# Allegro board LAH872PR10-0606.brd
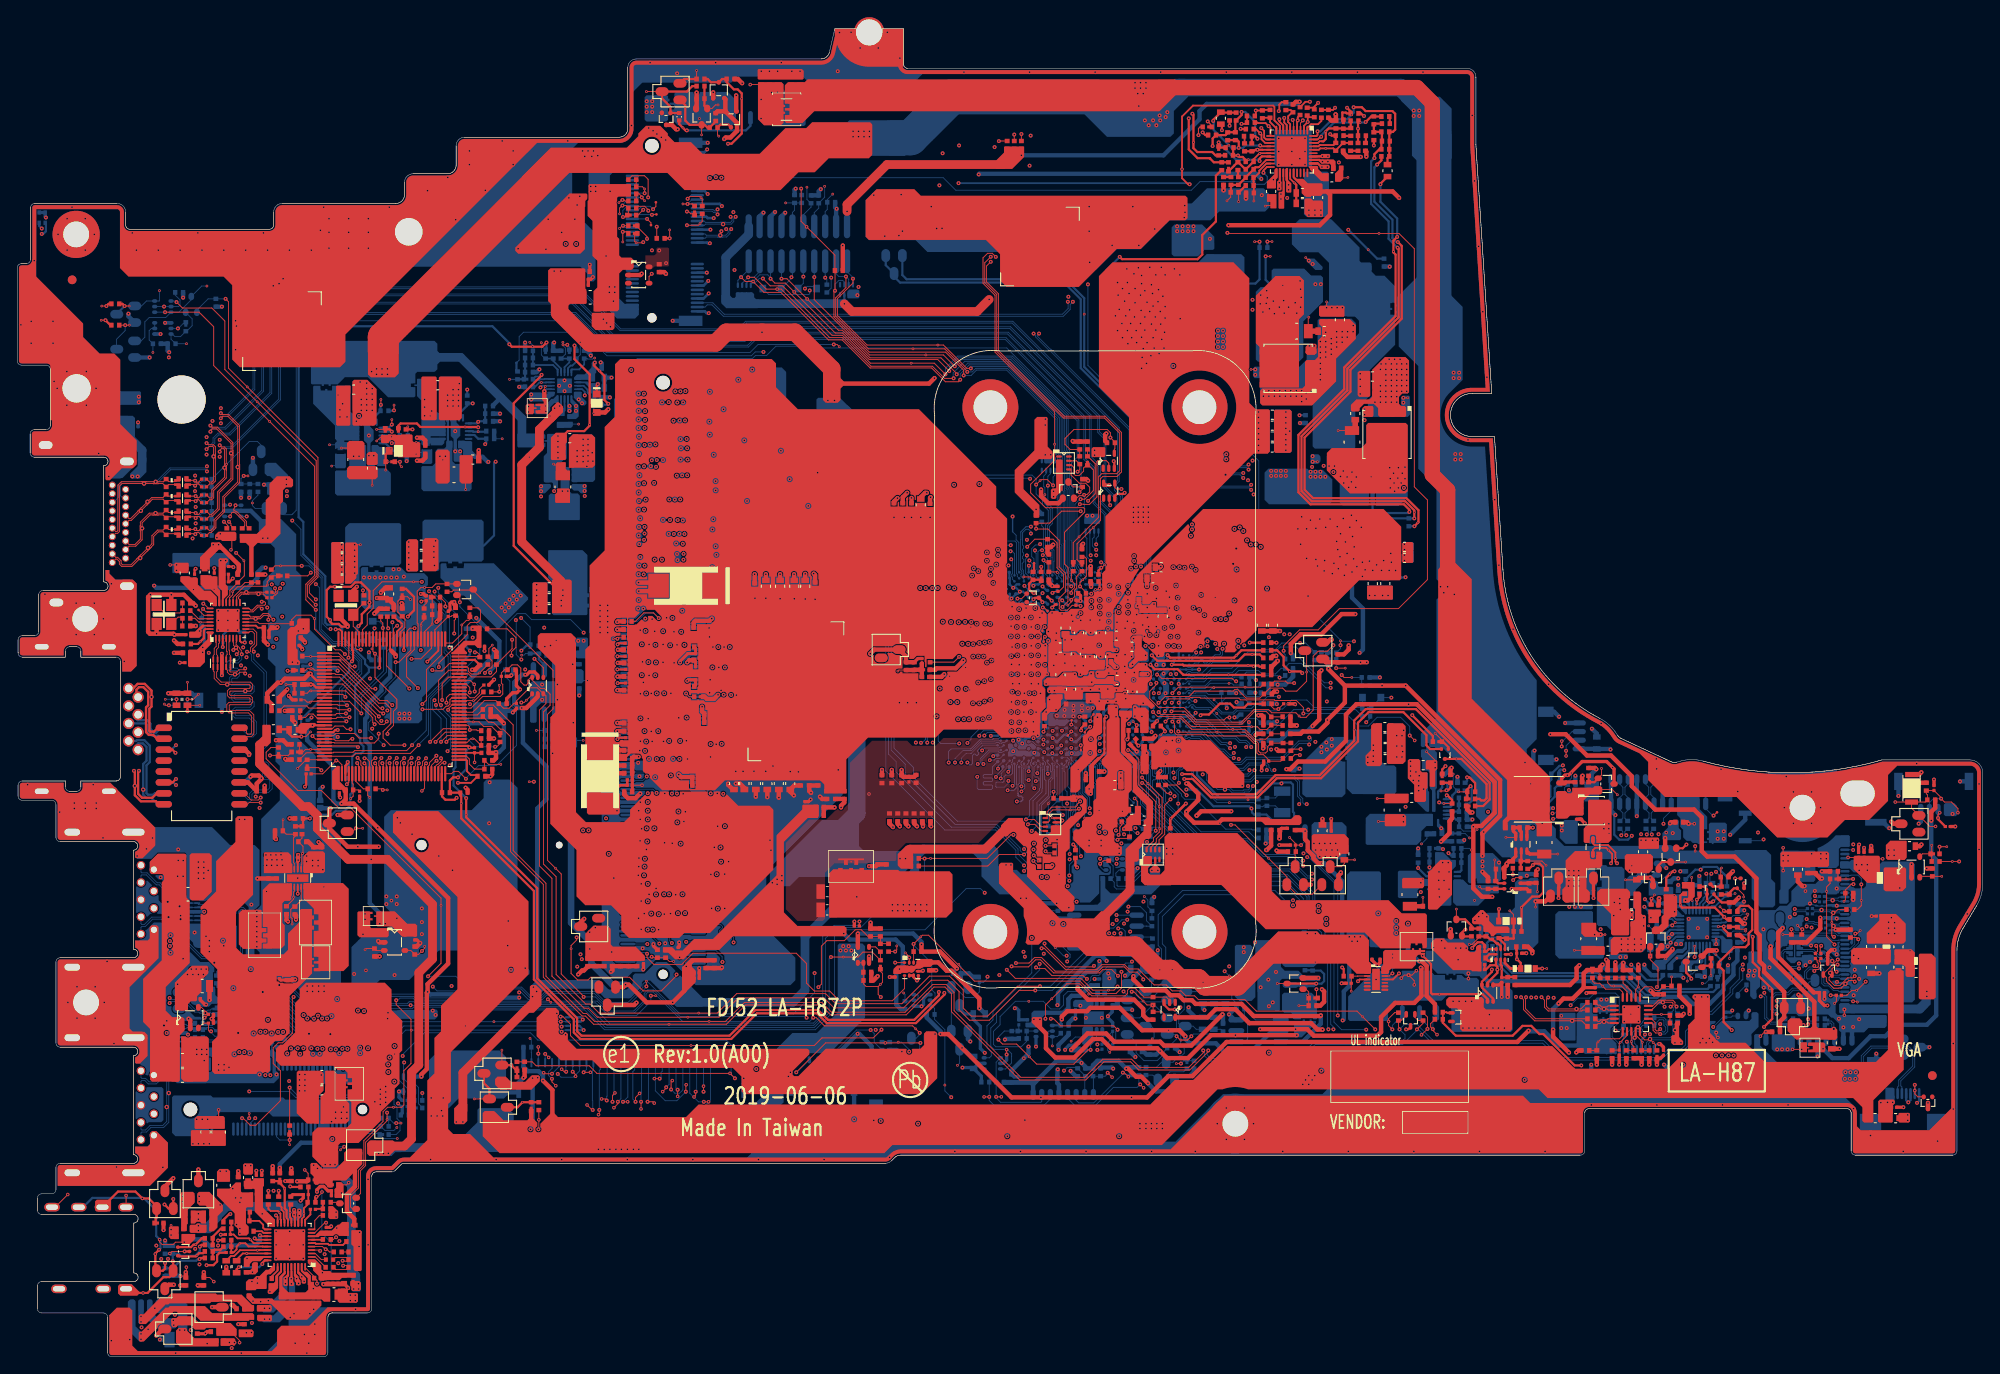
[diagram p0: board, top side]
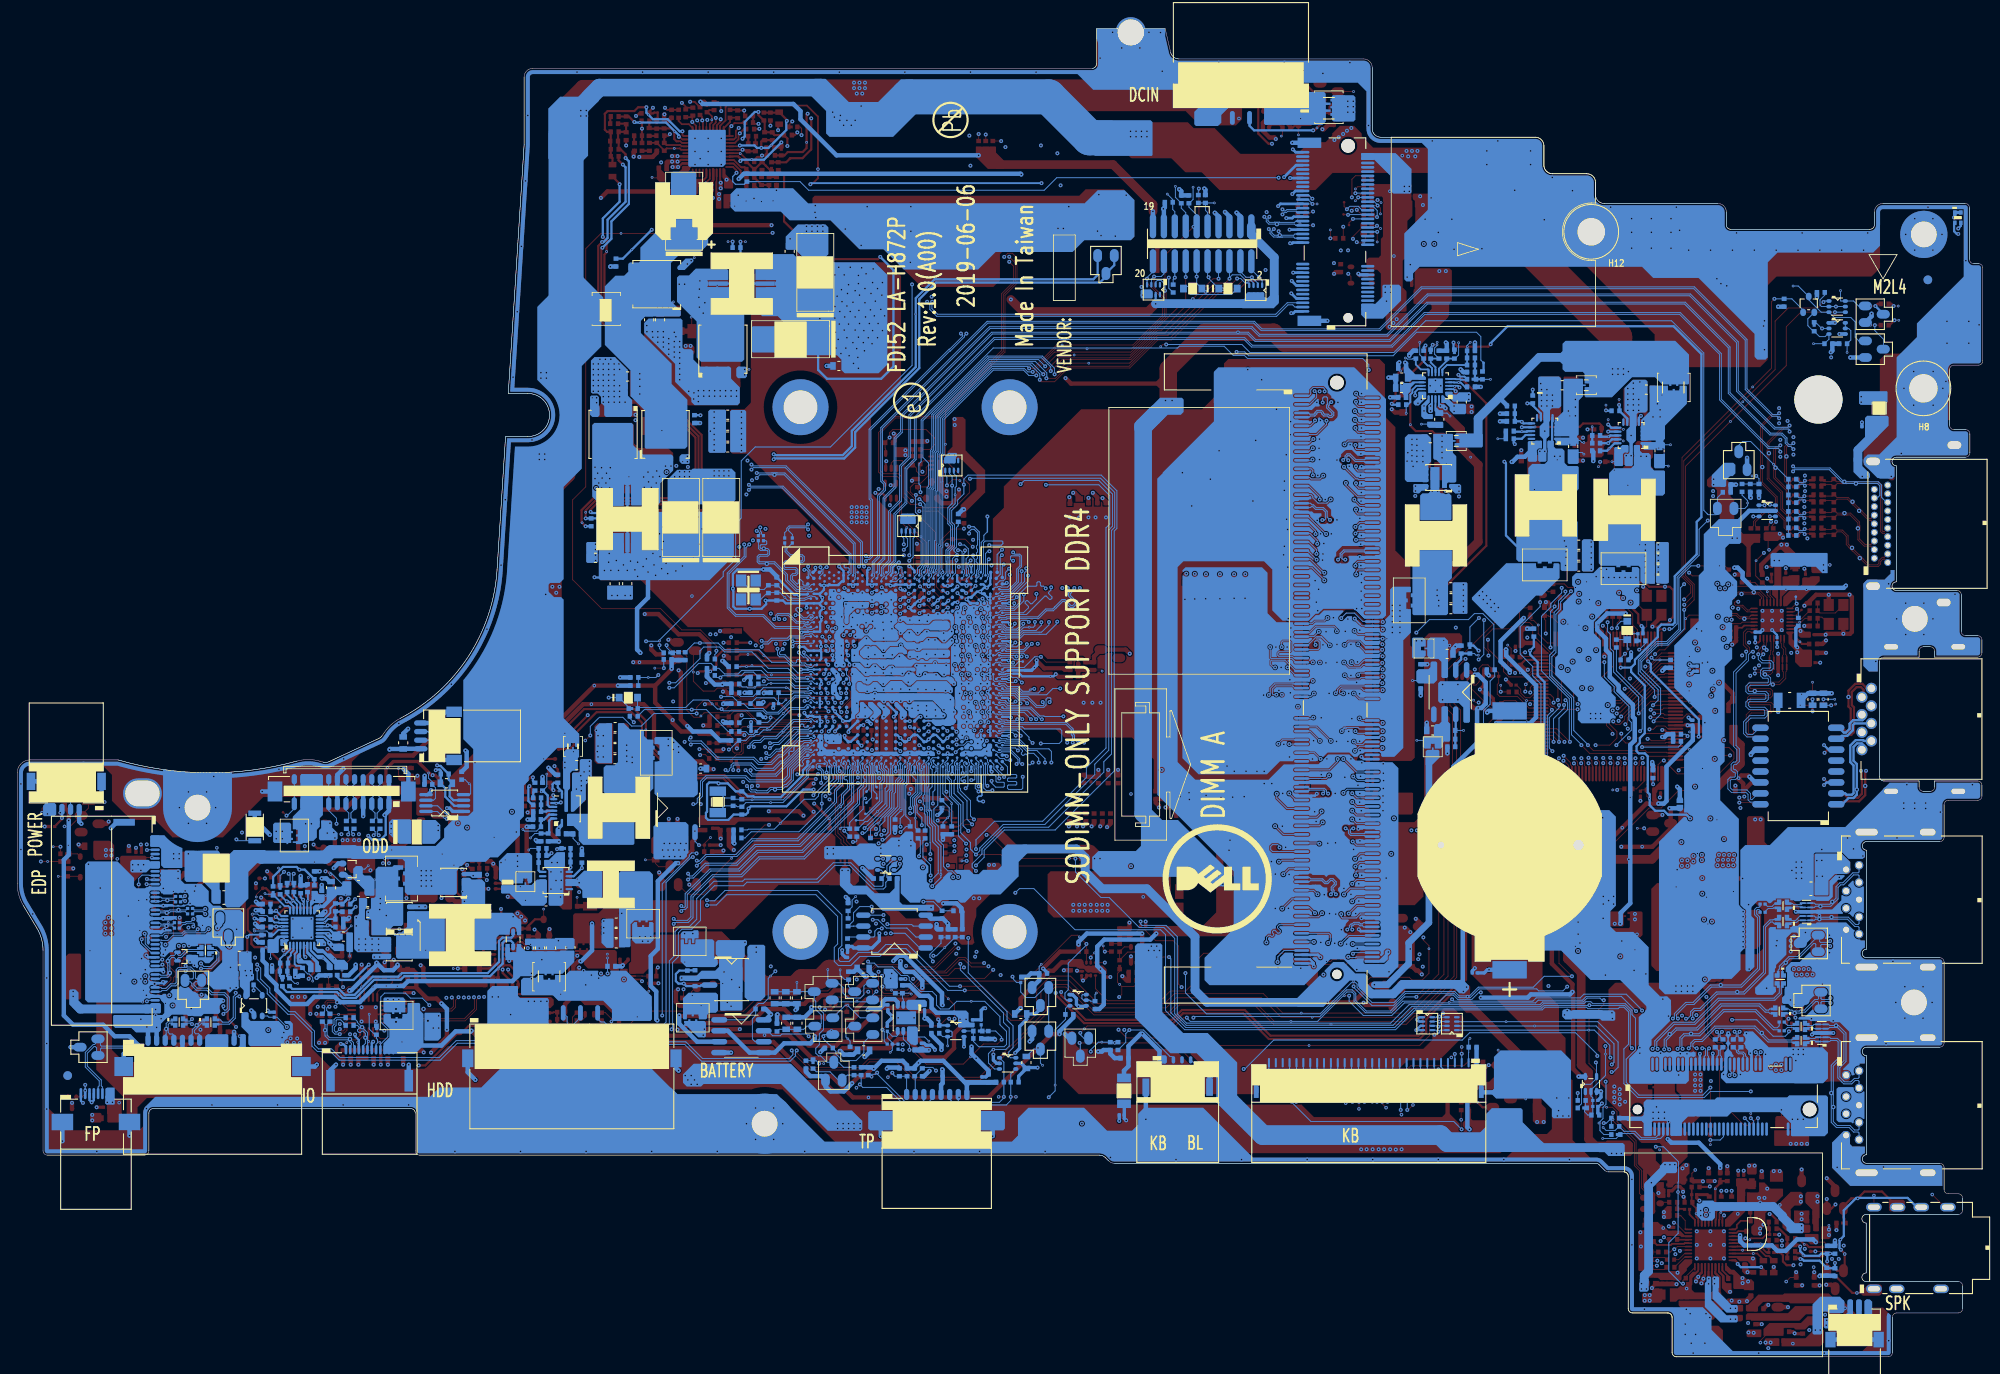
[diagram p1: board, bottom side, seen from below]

Outline 228.4 x 154.4 mm; copper layers: TOP, VCC, IN1, IN2, GND, BOTTOM. Coordinates in mm from the lower left corner of the outline.

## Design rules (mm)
net group APU_CLK(SINGLE): nets 48M_X1 48M_X2
net group APU_DP1_P0: nets APU_DP1_N0 APU_DP1_P0
net group APU_DP1_P1: nets APU_DP1_N1 APU_DP1_P1
net group APU_DP1_P2: nets APU_DP1_N2 APU_DP1_P2
net group APU_DP1_P3: nets APU_DP1_N3 APU_DP1_P3
net group APU_DP1CSO: nets CSON CSOP
net group AUDIO: nets LINE1-L_C LINE1-L_R
net group DDR_A_CLK0: nets DDR_A_CLK0 DDR_A_CLK#0
net group DDR_A_CLK1: nets DDR_A_CLK1 DDR_A_CLK#1
net group DDR_CTRL: nets DDR_A_CKE0 DDR_A_CKE1
net group DIFFPAIR0: nets DDR_A_DQS3 DDR_A_DQS#3
net group DIFFPAIR1: nets DDR_A_DQS2 DDR_A_DQS#2
net group DIFFPAIR2: nets DDR_A_DQS1 DDR_A_DQS#1
net group DIFFPAIR3: nets DDR_A_DQS0 DDR_A_DQS#0
net group DIFFPAIR4: nets DDR_A_DQS4 DDR_A_DQS#4
net group DIFFPAIR5: nets DDR_A_DQS5 DDR_A_DQS#5
net group DIFFPAIR6: nets DDR_A_DQS6 DDR_A_DQS#6
net group DIFFPAIR7: nets DDR_A_DQS7 DDR_A_DQS#7
net group I2C_0_SDA_R: nets I2C_0_SCL_R I2C_0_SDA_R
net group LAN_MDIP0: nets LAN_MDIN0 LAN_MDIP0
net group LAN_MDIP1: nets LAN_MDIN1 LAN_MDIP1
net group LAN_MDIP2: nets LAN_MDIN2 LAN_MDIP2
net group LAN_MDIP3: nets LAN_MDIN3 LAN_MDIP3
net group NCT7718_DX: nets NCT7718_DXN NCT7718_DXP
net group PCIE_ARX_DTX_P1: nets PCIE_ARX_DTX_N1 PCIE_ARX_DTX_P1
net group PCIE_ARX_DTX_P2: nets PCIE_ARX_DTX_N2 PCIE_ARX_DTX_P2
net group PCIE_ARX_DTX_P3: nets PCIE_ARX_DTX_N3 PCIE_ARX_DTX_P3
net group PCIE_ATX_C_DRX_P2: nets PCIE_ATX_C_DRX_N2 PCIE_ATX_C_DRX_P2
net group PCIE_ATX_C_DRX_P3: nets PCIE_ATX_C_DRX_N3 PCIE_ATX_C_DRX_P3
net group PCIE_ATX_DRX_P2: nets PCIE_ATX_DRX_N2 PCIE_ATX_DRX_P2
net group PCIE_ATX_DRX_P3: nets PCIE_ATX_DRX_N3 PCIE_ATX_DRX_P3
net group SATA_ARX_C_DTX_P0: nets SATA_ARX_C_DTX_N0 SATA_ARX_C_DTX_P0
net group SATA_ARX_C_DTX_P1: nets SATA_ARX_C_DTX_N1 SATA_ARX_C_DTX_P1
net group SATA_ARX_C_RD_DTX_P0: nets SATA_ARX_C_RD_DTX_N0 SATA_ARX_C_RD_DTX_P0
net group SATA_ARX_DTX_P00: nets SATA_ARX_DTX_N0 SATA_ARX_DTX_P0
net group SATA_ARX_DTX_P1: nets SATA_ARX_DTX_N1 SATA_ARX_DTX_P1
net group SATA_ARX_RD_DTX_P0: nets SATA_ARX_RD_DTX_N0 SATA_ARX_RD_DTX_P0
net group SATA_ATX_C_DRX_P0: nets SATA_ATX_C_DRX_N0 SATA_ATX_C_DRX_P0
net group SATA_ATX_C_DRX_P1: nets SATA_ATX_C_DRX_N1 SATA_ATX_C_DRX_P1
net group SATA_ATX_C_RD_DRX_P0: nets SATA_ATX_C_RD_DRX_N0 SATA_ATX_C_RD_DRX_P0
net group SATA_ATX_DRX_P0: nets SATA_ATX_DRX_N0 SATA_ATX_DRX_P0
net group SATA_ATX_DRX_P1: nets SATA_ATX_DRX_N1 SATA_ATX_DRX_P1
net group SATA_ATX_RD_DRX_P0: nets SATA_ATX_RD_DRX_N0 SATA_ATX_RD_DRX_P0
net group USB20_P3_R: nets USB20_N3_R USB20_P3_R
net group APU_CLK_13/16: nets CLK_PCIE_N0 CLK_PCIE_N1 CLK_PCIE_N2 CLK_PCIE_P0 CLK_PCIE_P1 CLK_PCIE_P2
net group DDR_ADD: nets DDR_A_ACT# DDR_A_ADD0 DDR_A_ADD1 DDR_A_ADD2 DDR_A_ADD3 DDR_A_ADD4 DDR_A_ADD5 DDR_A_ADD6 DDR_A_ADD7 DDR_A_ADD8 DDR_A_ADD9 DDR_A_ADD10 DDR_A_ADD11 DDR_A_ADD12 DDR_A_ADD13 DDR_A_BA0 DDR_A_BA1 DDR_A_BG0 DDR_A_BG1 DDR_A_CAS# DDR_A_RAS# DDR_A_WE#
net group DDR_D0: nets DDR_A_DM0 DDR_A_DQ0 DDR_A_DQ1 DDR_A_DQ2 DDR_A_DQ3 DDR_A_DQ4 DDR_A_DQ5 DDR_A_DQ6 DDR_A_DQ7
net group DDR_D1: nets DDR_A_DM1 DDR_A_DQ8 DDR_A_DQ9 DDR_A_DQ10 DDR_A_DQ11 DDR_A_DQ12 DDR_A_DQ13 DDR_A_DQ14 DDR_A_DQ15
net group DDR_D2: nets DDR_A_DM2 DDR_A_DQ16 DDR_A_DQ17 DDR_A_DQ18 DDR_A_DQ19 DDR_A_DQ20 DDR_A_DQ21 DDR_A_DQ22 DDR_A_DQ23
net group DDR_D3: nets DDR_A_DM3 DDR_A_DQ24 DDR_A_DQ25 DDR_A_DQ26 DDR_A_DQ27 DDR_A_DQ28 DDR_A_DQ29 DDR_A_DQ30 DDR_A_DQ31
net group DDR_D4: nets DDR_A_DM4 DDR_A_DQ32 DDR_A_DQ33 DDR_A_DQ34 DDR_A_DQ35 DDR_A_DQ36 DDR_A_DQ37 DDR_A_DQ38 DDR_A_DQ39
net group DDR_D5: nets DDR_A_DM5 DDR_A_DQ40 DDR_A_DQ41 DDR_A_DQ42 DDR_A_DQ43 DDR_A_DQ44 DDR_A_DQ45 DDR_A_DQ46 DDR_A_DQ47
net group DDR_D6: nets DDR_A_DM6 DDR_A_DQ48 DDR_A_DQ49 DDR_A_DQ50 DDR_A_DQ51 DDR_A_DQ52 DDR_A_DQ53 DDR_A_DQ54 DDR_A_DQ55
net group DDR_D7: nets DDR_A_DM7 DDR_A_DQ56 DDR_A_DQ57 DDR_A_DQ58 DDR_A_DQ59 DDR_A_DQ60 DDR_A_DQ61 DDR_A_DQ62 DDR_A_DQ63
net group DDR_MISC: nets DDR_A_CS0# DDR_A_CS1# DDR_A_EVENT# DDR_A_ODT0 DDR_A_ODT1 DDR_A_RST#
net group DP1-DATA: nets HDMI_CLKN HDMI_CLKP HDMI_L_CLKN HDMI_L_CLKP HDMI_L_TX_N0 HDMI_L_TX_N1 HDMI_L_TX_N2 HDMI_L_TX_P0 HDMI_L_TX_P1 HDMI_L_TX_P2 HDMI_TX_N0 HDMI_TX_N1 HDMI_TX_N2 HDMI_TX_P0 HDMI_TX_P1 HDMI_TX_P2
net group DP-AUX: nets APU_DP1_CTRL_CLK APU_DP1_CTRL_DATA EDP_AUXN EDP_AUXN_C EDP_AUXP EDP_AUXP_C HDMI_CTRL_CLK HDMI_CTRL_DATA
net group EDP: nets EDP_TXN0 EDP_TXN0_C EDP_TXN1 EDP_TXN1_C EDP_TXP0 EDP_TXP0_C EDP_TXP1 EDP_TXP1_C
net group HDA: nets HDA_BIT_CLK HDA_BIT_CLK_R HDA_RST# HDA_SDIN0 HDA_SDIN1 HDA_SDIN2 HDA_SDOUT HDA_SDOUT_R HDA_SYNC HDA_SYNC_R
net group HDA_JACK: nets RING2_R SLEEVE SLEEVE_R
net group I2C: nets A_MIC_CLK A_MIC_DATA I2C_0_SCL I2C_0_SDA I2C_1_SCL I2C_1_SDA I2C_3_SCL I2C_3_SCL_R I2C_3_SDA I2C_3_SDA_R
net group KB: nets KSI0 KSI1 KSI2 KSI3 KSI4 KSI5 KSI6 KSI7 KSO0 KSO1 KSO2 KSO3 KSO4 KSO5 KSO6 KSO7 KSO8 KSO9 KSO10 KSO11 KSO12 KSO13 KSO14 KSO15 KSO16
net group LPC: nets LPC_AD0 LPC_AD1 LPC_AD2 LPC_AD3 LPC_CLK0_EC LPC_CLK1 LPC_FRAME# LPC_RST_A# LPCPD# SERIRQ
net group PCIE: nets PCIE_ARX_C_DTX_N0 PCIE_ARX_C_DTX_P0 PCIE_ARX_DTX_N0 PCIE_ARX_DTX_P0 PCIE_ATX_C_DRX_N0 PCIE_ATX_C_DRX_N1 PCIE_ATX_C_DRX_P0 PCIE_ATX_C_DRX_P1 PCIE_ATX_DRX_N0 PCIE_ATX_DRX_N1 PCIE_ATX_DRX_P0 PCIE_ATX_DRX_P1
net group RJ45_LAN: nets RJ45_MDIN0 RJ45_MDIN1 RJ45_MDIN2 RJ45_MDIN3 RJ45_MDIP0 RJ45_MDIP1 RJ45_MDIP2 RJ45_MDIP3
net group SM: nets APU_SCLK0 APU_SDATA0 CLK_SMB DAT_SMB EC_SMB_CK1 EC_SMB_CK2 EC_SMB_DA1 EC_SMB_DA2
net group SPI: nets APU_SPI_CLK APU_SPI_CLK_R APU_SPI_CS1# APU_SPI_CS1#_R APU_SPI_HOLD# APU_SPI_MISO APU_SPI_MOSI APU_SPI_TPMCS# APU_SPI_WP#
net group USB2: nets USB20_N0 USB20_N0_R USB20_N1 USB20_N1_R USB20_N2 USB20_N3 USB20_N4 USB20_N5 USB20_N5_R USB20_N6 USB20_N6_R USB20_N7 USB20_P0 USB20_P0_R USB20_P1 USB20_P1_R USB20_P2 USB20_P3 USB20_P4 USB20_P5 USB20_P5_R USB20_P6 USB20_P6_R USB20_P7
net group USB3: nets USB3_ARX_DTX_0_N1 USB3_ARX_DTX_0_N1_R USB3_ARX_DTX_0_N2 USB3_ARX_DTX_0_N2_R USB3_ARX_DTX_0_P1 USB3_ARX_DTX_0_P1_R USB3_ARX_DTX_0_P2 USB3_ARX_DTX_0_P2_R USB3_ATX_C_DRX_0_N1 USB3_ATX_C_DRX_0_N2 USB3_ATX_C_DRX_0_P1 USB3_ATX_C_DRX_0_P2 USB3_ATX_DRX_0_N1 USB3_ATX_DRX_0_N2 USB3_ATX_DRX_0_P1 USB3_ATX_DRX_0_P2 USB3_ATX_L_DRX_0_N1 USB3_ATX_L_DRX_0_N2 USB3_ATX_L_DRX_0_P1 USB3_ATX_L_DRX_0_P2
nets with their own width: min track width 0.254; nets +3VALWP +5VALWP BATGONE BMON CCLIM COMP CSIN_CHG CSIP_CHG EN_5V ENLDO_3V5V FB_5V FB_5V_R HW_ACAV_IN N17389450 N28483977 N28484391 N28484500 N28866422 N28866613 N38653708 N39173777 N39173785 N48572179 NTC_CHG SUSP# VBAT
nets with their own width: min track width 0.381; nets N28484416 N28484451
nets with their own width: min track width 0.508; nets +1.2V_DDR +2.5V_MEM +3VALW +3VALW_EC +3VLP +3VS_CAM +3VS_TOUCH +5VALW +19V_VIN +19VB +EC_VCCA +MEM_VREF +RTC_APU +RTC_APU_R +RTCBATT ASGATE BA BGATE CMSRC ECAGND GND LOM_TCT N29179188
nets with their own width: min track width 0.762; nets LG_1.2V LG_CHG LX_1.2V LX_CHG UG_1.2V UG_CHG
nets with their own width: min track width 1.016; nets 5VS +0.95VALW +0.775VALW +1.8V_ALW +1.8VS +3V_DVDD +3VS +5V_AVDD +5V_HDMI +5VS +LCDVDD
nets with their own width: min track width 1.524; nets +3VS_SSD +5V_HDD +5VS_ODD

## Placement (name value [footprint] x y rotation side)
C1  5.6P_0402_50V8D  [C_0402]  140.13 88.85 270 bottom
C2  5.6P_0402_50V8D  [C_0402]  140.13 89.71 90 bottom
C3  4.7U_0603_6.3V6K  [C_0603]  215.43 45.97 270 top
C4  1U_0201_6.3V6M  [C_0201]  116.3 32.55 270 bottom
C5  1U_0201_6.3V6M  [C_0201]  99.75 28.13 0 bottom
C6  10U_0402_6.3V6M  [C_0402]  99.27 34.73 0 bottom
C7  100P_0402_50V8J  [C_0402]  125.89 32.62 90 bottom
C8  100P_0402_50V8J  [C_0402]  123.22 33.54 270 bottom
C9  0.1U_0201_10V6K  [C_0201]  111.79 44.1 270 bottom
C10  10U_0402_6.3V6M  [C_0402]  92.81 63.89 0 top
C11  0.1U_0201_10V6K  [C_0201]  91.54 63.97 90 top
C12  470P_0603_50V8J  [C_0603]  179.23 66.68 180 bottom
C13  2200P_0402_50V7K  [C_0402]  179.18 67.76 180 bottom
C14  0.1U_0201_10V6K  [C_0201]  58.01 75.98 270 top
C15  0.1U_0201_10V6K  [C_0201]  56.26 79.12 0 top
C16  0.01U_0402_16V7K  [C_0402]  33.59 59.89 180 top
C17  470P_0402_50V7K  [C_0402]  32.27 52.34 270 top
C18  0.1U_0201_10V6K  [C_0201]  30.45 44.55 270 top
C19  10U_0402_6.3V6M  [C_0402]  31.34 44.71 270 top
C20  330P_0402_50V7K  [C_0402]  158.9 45.4 0 bottom
C21  1U_0201_6.3V6M  [C_0201]  154.43 43.43 0 top
C22  1U_0201_6.3V6M  [C_0201]  156.84 46.22 0 top
C23  0.1U_0201_10V6K  [C_0201]  158.95 46.22 180 top
C24  470P_0402_50V7K  [C_0402]  31.29 52.38 270 top
C25  0.01U_0402_16V7K  [C_0402]  29.96 61.16 0 top
C26  0.1U_0201_10V6K  [C_0201]  32.19 82.71 0 top
C27  10U_0402_6.3V6M  [C_0402]  32.03 83.6 0 top
C28  4.7U_0603_6.3V6K  [C_0603]  149.7 68.38 180 bottom
C29  4.7U_0603_6.3V6K  [C_0603]  151.67 60.45 90 top
C30  1U_0201_6.3V6M  [C_0201]  152.69 60.54 90 top
C31  10U_0402_6.3V6M  [C_0402]  30.13 56.52 270 top
C32  10U_0402_6.3V6M  [C_0402]  29.18 56.52 270 top
C33  10U_0402_6.3V6M  [C_0402]  34.45 58.34 90 top
C34  10U_0402_6.3V6M  [C_0402]  35.4 58.34 90 top
C35  0.1U_0201_10V6K  [C_0201]  148.54 59.49 180 top
C36  4.7U_0603_6.3V6K  [C_0603]  130.8 45.15 180 bottom
C37  22U_0603_6.3V6M  [C_0603]  140.39 42.44 270 bottom
C38  22U_0603_6.3V6M  [C_0603]  139.04 38.08 90 bottom
C39  4.7U_0603_6.3V6K  [C_0603]  137.8 42.44 270 bottom
C40  4.7U_0603_6.3V6K  [C_0603]  139.09 42.44 270 bottom
C41  0.1U_0201_10V6K  [C_0201]  123.33 35.87 90 bottom
C42  1U_0201_6.3V6M  [C_0201]  122.98 40.92 270 bottom
C43  4.7U_0603_6.3V6K  [C_0603]  130.75 35.62 180 bottom
C44  4.7U_0603_6.3V6K  [C_0603]  137.75 38.08 90 bottom
C45  1U_0201_6.3V6M  [C_0201]  117.4 38.6 90 bottom
C46  0.1U_0201_10V6K  [C_0201]  116.38 38.6 90 bottom
C47  0.1U_0201_10V6K  [C_0201]  127.29 37.85 90 bottom
C48  1U_0201_6.3V6M  [C_0201]  127.23 40.92 270 bottom
C49  1U_0201_6.3V6M  [C_0201]  126.35 43.93 180 bottom
C53  22U_0603_6.3V6M  [C_0603]  183.55 70.67 90 bottom
CA2  0.1U_0201_10V6K  [C_0201]  34.39 6.89 270 top
CA3  10U_0402_6.3V6M  [C_0402]  32.23 7.11 270 top
CA25  1U_0603_16V7  [C_0603]  24.29 11.17 270 top
CA26  10U_0402_6.3V6M  [C_0402]  31.78 17.71 90 top
CA27  1000P_0402_50V7K  [C_0402]  26.39 4.71 270 top
CA28  1000P_0402_50V7K  [C_0402]  26.4 5.58 180 top
CA43  68P_0201_50V8J  [C_0201]  30.64 6.89 270 top
CA44  68P_0201_50V8J  [C_0201]  36.1 9.11 270 top
CA45  68P_0201_50V8J  [C_0201]  27.78 20.53 90 top
CA46  68P_0201_50V8J  [C_0201]  37.09 19.3 180 top
CA47  10P_0201_50V8J  [C_0201]  35.02 6.89 270 top
CA48  10P_0201_50V8J  [C_0201]  37.25 9.11 270 top
CA49  10P_0201_50V8J  [C_0201]  28.42 20.53 90 top
CA50  10P_0201_50V8J  [C_0201]  37.09 18.73 180 top
CA51  0.1U_0402_25V6  [C_0402]  25.69 19.99 90 top
CA52  0.1U_0402_25V6  [C_0402]  31.85 20.43 90 top
CA53  0.1U_0402_25V6  [C_0402]  19.59 9.22 270 top
CA474  0.1U_0201_10V6K  [C_0201]  31.28 6.89 270 top
CA475  0.1U_0201_10V6K  [C_0201]  27.8 18.92 180 top
CA476  1000P_0402_50V7K  [C_0402]  20.93 1.79 90 top
CA477  10U_0402_6.3V6M  [C_0402]  38.25 14.35 0 top
CA478  0.1U_0201_10V6K  [C_0201]  34.65 17.14 180 top
CA479  10U_0402_6.3V6M  [C_0402]  26.07 15.81 0 top
CA480  1000P_0402_50V7K  [C_0402]  23.41 2.92 180 top
CA481  10U_0402_6.3V6M  [C_0402]  28.04 17.84 180 top
CA482  10U_0402_6.3V6M  [C_0402]  28.66 9.1 0 top
CA483  10U_0402_6.3V6M  [C_0402]  38.01 9.47 270 top
CA484  10U_0402_6.3V6M  [C_0402]  26.64 10.74 270 top
CA485  0.1U_0201_10V6K  [C_0201]  36.67 9.11 270 top
CA486  22P_0402_50V8J  [C_0402]  38.5 11.3 0 top
CA487  33P_0402_50V8J  [C_0402]  39.42 12.19 180 top
CA488  0.1U_0201_10V6K  [C_0201]  33.83 18.85 180 top
CA489  2.2U_0402_6.3V6M  [C_0402]  27.47 14.6 180 top
CA490  0.1U_0201_10V6K  [C_0201]  35.91 14.46 90 top
CA491  22P_0402_50V8J  [C_0402]  38.5 10.41 0 top
CA492  0.1U_0201_10V6K  [C_0201]  27.66 11.37 270 top
CA493  10U_0402_6.3V6M  [C_0402]  39.16 13.39 180 top
CA494  10U_0402_6.3V6M  [C_0402]  33.44 7.11 270 top
CA495  10U_0402_6.3V6M  [C_0402]  29.52 8.19 180 top
CA496  1U_0603_16V7  [C_0603]  25.5 9.77 90 top
CA497  680P_0402_50V8J  [C_0402]  22.59 16.7 180 top
CA498  100P_0402_50V8J  [C_0402]  18.07 11.98 90 bottom
CA499  680P_0402_50V8J  [C_0402]  19.52 15.81 0 top
CA500  10U_0402_6.3V6M  [C_0402]  29.18 17.71 90 top
CA501  680P_0402_50V8J  [C_0402]  22.59 15.81 180 top
CA502  680P_0402_50V8J  [C_0402]  19.52 16.7 0 top
CA503  10U_0402_6.3V6M  [C_0402]  30.39 17.71 90 top
CA504  100P_0402_50V8J  [C_0402]  17.18 10.3 270 bottom
CA505  330P_0201_50V7K  [C_0201]  24.77 14.22 180 top
CA506  330P_0201_50V7K  [C_0201]  24.87 12.13 180 top
CC1  0.1U_0201_10V6K  [C_0201]  139.22 94.62 90 bottom
CC2  0.1U_0201_10V6K  [C_0201]  138.33 94.62 90 bottom
CC3  1000P_0402_50V7K  [C_0402]  104.23 79.85 90 top
CC4  0.1U_0201_10V6K  [C_0201]  105.13 80.6 90 top
CC5  0.1U_0201_10V6K  [C_0201]  120.93 89.57 270 top
CC6  0.1U_0201_10V6K  [C_0201]  123.03 87.96 270 top
CC7  100P_0402_50V8J  [C_0402]  45.48 28.11 180 bottom
CC8  0.1U_0201_10V6K  [C_0201]  142.54 72.71 0 bottom
CC9  0.1U_0201_10V6K  [C_0201]  145.42 69.25 180 top
CC10  0.1U_0201_10V6K  [C_0201]  97.86 50.1 180 top
CC11  0.1U_0201_10V6K  [C_0201]  45.32 29.81 180 bottom
CC12  0.1U_0201_10V6K  [C_0201]  45.32 29.11 180 bottom
CC13  0.22U_0402_10V6K  [C_0402]  124.79 68.05 0 top
CC14  0.1U_0201_10V6K  [C_0201]  147.74 75.92 180 top
CC15  0.1U_0201_10V6K  [C_0201]  140.51 75.94 180 bottom
CC16  150P_0402_50V8J  [C_0402]  98.32 44.71 0 top
CC18  18P_0402_50V8J  [C_0402]  144.2 63.96 270 bottom
CC19  22P_0402_50V8J  [C_0402]  144.2 64.83 90 bottom
CC21  150P_0402_50V8J  [C_0402]  100.3 48.88 90 top
CC22  0.1U_0201_10V6K  [C_0201]  131.92 46.43 90 bottom
CC23  22U_0603_6.3V6M  [C_0603]  90.3 88.87 90 top
CC24  22U_0603_6.3V6M  [C_0603]  87 88.87 90 top
CC25  22U_0603_6.3V6M  [C_0603]  104.99 98.34 90 top
CC26  22U_0603_6.3V6M  [C_0603]  85.83 67.36 270 top
CC27  22U_0603_6.3V6M  [C_0603]  88.49 67.36 270 top
CC28  22U_0603_6.3V6M  [C_0603]  87.16 67.36 270 top
CC29  22U_0603_6.3V6M  [C_0603]  83.29 67.36 270 top
CC30  22U_0603_6.3V6M  [C_0603]  91.57 88.87 90 top
CC31  22U_0603_6.3V6M  [C_0603]  84.49 67.36 270 top
CC32  22U_0603_6.3V6M  [C_0603]  89.83 67.36 270 top
CC33  22U_0603_6.3V6M  [C_0603]  88.65 88.87 90 top
CC34  0.22U_0402_10V6K  [C_0402]  85.7 89.01 90 top
CC35  0.22U_0402_10V6K  [C_0402]  119.24 75.74 0 top
CC36  0.22U_0402_10V6K  [C_0402]  91.02 67.35 270 top
CC37  0.22U_0402_10V6K  [C_0402]  94.07 65.77 270 top
CC38  0.22U_0402_10V6K  [C_0402]  92.71 89.11 90 top
CC39  0.22U_0402_10V6K  [C_0402]  96.1 65.77 270 top
CC40  180P_0402_50V8J  [C_0402]  92.04 67.35 270 top
CC41  0.22U_0402_10V6K  [C_0402]  93.05 67.35 270 top
CC42  180P_0402_50V8J  [C_0402]  124.17 79.76 270 top
CC48  0.22U_0402_10V6K  [C_0402]  122.28 80.1 270 top
CC51  22U_0603_6.3V6M  [C_0603]  125.95 84.88 270 top
CC52  22U_0603_6.3V6M  [C_0603]  125.95 80.67 90 top
CC53  22U_0603_6.3V6M  [C_0603]  121.22 80.01 270 top
CC54  22U_0603_6.3V6M  [C_0603]  123.36 84.88 270 top
CC55  22U_0603_6.3V6M  [C_0603]  123 81 90 top
CC56  22U_0603_6.3V6M  [C_0603]  124.68 80.7 90 top
CC57  22U_0603_6.3V6M  [C_0603]  124.73 84.88 270 top
CC58  22U_0603_6.3V6M  [C_0603]  120.49 82.46 0 top
CC59  22U_0603_6.3V6M  [C_0603]  121.82 85.45 270 top
CC60  0.22U_0402_10V6K  [C_0402]  103.91 98.32 90 top
CC61  0.22U_0402_10V6K  [C_0402]  101.88 98.32 90 top
CC62  0.22U_0402_10V6K  [C_0402]  102.9 98.32 90 top
CC63  180P_0402_50V8J  [C_0402]  95.09 65.77 270 top
CC64  180P_0402_50V8J  [C_0402]  106.07 98.26 90 top
CC65  180P_0402_50V8J  [C_0402]  128.02 80.83 180 top
CC66  0.22U_0402_10V6K  [C_0402]  126.2 79.45 270 top
CC67  0.22U_0402_10V6K  [C_0402]  130.72 77.59 270 top
CC68  0.22U_0402_10V6K  [C_0402]  127.07 76.86 0 top
CC69  0.22U_0402_10V6K  [C_0402]  131.25 88.04 180 top
CC70  0.22U_0402_10V6K  [C_0402]  130.46 80.28 90 top
CC71  0.22U_0402_10V6K  [C_0402]  130.72 78.46 90 top
CC72  0.22U_0402_10V6K  [C_0402]  123.51 76.86 0 top
CC73  0.22U_0402_10V6K  [C_0402]  127.93 82.81 180 top
CC74  22U_0603_6.3V6M  [C_0603]  122.46 76.91 90 top
CC75  22U_0603_6.3V6M  [C_0603]  128.82 82.55 0 top
CC76  22U_0603_6.3V6M  [C_0603]  132.68 90.53 180 top
CC77  22U_0603_6.3V6M  [C_0603]  128.51 78.69 180 top
CC78  10U_0402_6.3V6M  [C_0402]  123.27 67.1 0 top
CC79  22U_0603_6.3V6M  [C_0603]  126.84 66.46 0 top
CC80  10U_0402_6.3V6M  [C_0402]  127.04 75.48 180 top
CC85  0.22U_0402_10V6K  [C_0402]  121.15 77.67 270 top
CC86  0.22U_0402_10V6K  [C_0402]  131.97 85.82 90 top
CC87  0.22U_0402_10V6K  [C_0402]  130.37 84.5 270 top
CC88  0.22U_0402_10V6K  [C_0402]  130.71 85.82 90 top
CC89  0.22U_0402_10V6K  [C_0402]  126.2 76.86 180 top
CC92  10U_0402_6.3V6M  [C_0402]  129.25 74.82 90 top
CC93  0.22U_0402_10V6K  [C_0402]  128.32 74.85 90 top
CC94  10U_0402_6.3V6M  [C_0402]  131.81 70.92 180 top
CC95  10U_0402_6.3V6M  [C_0402]  132.12 69.51 180 top
CC96  0.22U_0402_10V6K  [C_0402]  132.12 68.62 180 top
CC97  0.22U_0402_10V6K  [C_0402]  145.7 61.26 90 top
CC98  10U_0402_6.3V6M  [C_0402]  100.99 56.34 90 top
CC99  10U_0402_6.3V6M  [C_0402]  99.98 56.34 90 top
CC100  10U_0402_6.3V6M  [C_0402]  104.45 66.74 90 top
CC101  1U_0201_6.3V6M  [C_0201]  103.62 66.84 90 top
CC102  10U_0402_6.3V6M  [C_0402]  131.09 75.09 45 top
CC103  0.22U_0402_10V6K  [C_0402]  130.97 72.78 270 top
CC104  0.22U_0402_10V6K  [C_0402]  146.71 62.16 270 top
CC105  1U_0201_6.3V6M  [C_0201]  147.6 62.03 270 top
CC106  10U_0402_6.3V6M  [C_0402]  103.27 63.17 270 top
CC107  10U_0402_6.3V6M  [C_0402]  101.36 63.17 270 top
CC109  10U_0402_6.3V6M  [C_0402]  121.88 75.9 180 top
CC110  0.22U_0402_10V6K  [C_0402]  104.22 63.17 270 top
CC111  180P_0402_50V8J  [C_0402]  102.77 66.7 90 top
CC112  0.22U_0402_10V6K  [C_0402]  105.17 63.17 270 top
CC113  0.22U_0402_10V6K  [C_0402]  106.12 63.17 270 top
CC114  0.22U_0402_10V6K  [C_0402]  100.48 66.7 90 top
CC115  0.22U_0402_10V6K  [C_0402]  102.31 63.17 270 top
CC116  0.22U_0402_10V6K  [C_0402]  101.63 66.7 90 top
CC119  0.1U_0201_10V6K  [C_0201]  209.42 42.35 0 top
CC120  680P_0603_50V8J  [C_0603]  210.85 37.21 270 top
CC121  10P_0402_50V8J  [C_0402]  131.85 51.84 90 bottom
CC122  22U_0603_6.3V6M  [C_0603]  133.64 91.79 180 top
CC123  22U_0603_6.3V6M  [C_0603]  144.62 85.78 270 top
CC124  22U_0603_6.3V6M  [C_0603]  145.91 85.78 270 top
CC125  22U_0603_6.3V6M  [C_0603]  133.1 85.39 90 top
CC126  22U_0603_6.3V6M  [C_0603]  128.43 83.85 180 top
CC127  22U_0603_6.3V6M  [C_0603]  160.5 92.9 0 bottom
CC129  22U_0603_6.3V6M  [C_0603]  129.59 78.05 270 top
CC130  0.1U_0201_10V6K  [C_0201]  58.73 44.64 0 bottom
CD1  100P_0402_50V8J  [C_0402]  71.39 85.51 180 top
CD2  10U_0402_6.3V6M  [C_0402]  79.52 84.81 180 top
CD3  10U_0402_6.3V6M  [C_0402]  79.36 66.45 180 top
CD4  10U_0402_6.3V6M  [C_0402]  78.92 73.76 0 top
CD5  10U_0402_6.3V6M  [C_0402]  71.45 70.52 180 top
CD6  10U_0402_6.3V6M  [C_0402]  71.39 84.55 180 top
CD7  10U_0402_6.3V6M  [C_0402]  71.45 73.7 180 top
CD8  1U_0201_6.3V6M  [C_0201]  79.41 78.71 180 top
CD9  1U_0201_6.3V6M  [C_0201]  71.29 78.33 180 top
CD10  1U_0201_6.3V6M  [C_0201]  79.41 80.24 180 top
CD11  1U_0201_6.3V6M  [C_0201]  79.41 81.76 180 top
CD12  1U_0201_6.3V6M  [C_0201]  71.29 79.92 180 top
CD13  1U_0201_6.3V6M  [C_0201]  71.29 71.98 180 top
CD14  1U_0201_6.3V6M  [C_0201]  71.22 82.97 180 top
CD15  1U_0201_6.3V6M  [C_0201]  71.22 81.44 180 top
CD16  1U_0201_6.3V6M  [C_0201]  72.77 46.3 270 top
CD17  10U_0402_6.3V6M  [C_0402]  67.25 46.34 270 top
CD18  10U_0402_6.3V6M  [C_0402]  68.2 46.34 270 top
CD19  10P_0402_50V8J  [C_0402]  71.45 72.74 180 top
CD20  0.1U_0201_10V6K  [C_0201]  71.48 66.46 180 top
CD21  0.1U_0201_10V6K  [C_0201]  71.48 67.09 180 top
CD22  10P_0402_50V8J  [C_0402]  78.92 74.77 0 top
CD23  10P_0402_50V8J  [C_0402]  79.58 82.52 180 top
CD24  10P_0402_50V8J  [C_0402]  71.45 77.51 180 top
CD25  10P_0402_50V8J  [C_0402]  71.45 80.68 180 top
CD26  10P_0402_50V8J  [C_0402]  72.01 46.34 270 top
CD27  10P_0402_50V8J  [C_0402]  70.1 46.34 270 top
CD28  4.7U_0402_6.3V6K  [C_0402]  71.45 65.69 180 top
CD29  2.2U_0402_6.3V6M  [C_0402]  71.39 82.2 180 top
CD30  2.2U_0402_6.3V6M  [C_0402]  71.45 79.09 180 top
CD31  2.2U_0402_6.3V6M  [C_0402]  79.58 77.95 180 top
CD32  2.2U_0402_6.3V6M  [C_0402]  79.58 81 180 top
CD33  2.2U_0402_6.3V6M  [C_0402]  79.36 67.39 180 top
CD34  2.2U_0402_6.3V6M  [C_0402]  69.15 46.34 270 top
CD35  2.2U_0402_6.3V6M  [C_0402]  71.06 46.34 270 top
CD36  1000P_0402_50V7K  [C_0402]  71.45 67.85 180 top
CD37  330U_D2_2VY_R9M  [C_D3]  80.92 89.66 180 top
CD38  330U_D3_2.5VY_R6M  [C_D3]  67.73 70.7 270 top
CD39  1U_0201_6.3V6M  [C_0201]  78.67 44.64 0 top
CD40  10U_0402_6.3V6M  [C_0402]  80.02 46.11 270 top
CD41  10U_0402_6.3V6M  [C_0402]  80.99 46.11 270 top
CD42  1U_0201_6.3V6M  [C_0201]  76.81 47.01 90 top
CD43  1U_0201_6.3V6M  [C_0201]  78.67 44 0 top
CD44  10P_0402_50V8J  [C_0402]  66.29 46.34 270 top
CE1  0.1U_0201_10V6K  [C_0201]  37.44 66.14 270 top
CE2  0.1U_0201_10V6K  [C_0201]  53.72 82.61 0 top
CE3  0.1U_0201_10V6K  [C_0201]  33.18 79.71 90 bottom
CE4  0.1U_0201_10V6K  [C_0201]  33.69 73.43 90 bottom
CE5  0.1U_0201_10V6K  [C_0201]  53.15 70.23 90 top
CE7  100P_0402_50V8J  [C_0402]  50.28 65.59 180 top
CE8  22P_0402_50V8J  [C_0402]  32.22 78.16 0 top
CE9  100P_0402_50V8J  [C_0402]  48.22 87.31 0 top
CE10  100P_0402_50V8J  [C_0402]  44.74 87 270 top
CE11  0.1U_0201_10V6K  [C_0201]  50.08 86.08 90 top
CE12  680P_0402_50V7K  [C_0402]  53.76 81.35 270 top
CE13  10P_0402_50V8J  [C_0402]  48.22 86.29 0 top
CE14  0.1U_0201_10V6K  [C_0201]  47.53 87.9 90 top
CE15  0.1U_0201_10V6K  [C_0201]  32.97 76.39 180 top
CE16  0.1U_0201_10V6K  [C_0201]  40.08 84.07 180 bottom
CE17  0.1U_0201_10V6K  [C_0201]  34.16 67.78 180 top
CE18  0.1U_0201_10V6K  [C_0201]  222.73 65.84 90 top
CE19  0.1U_0201_10V6K  [C_0201]  39.79 65.76 270 top
CH1  0.01U_0402_16V7K  [C_0402]  90.33 134.16 90 bottom
CH2  0.01U_0402_16V7K  [C_0402]  95.02 126.3 0 top
CL1  12P_0402_50V8J  [C_0402]  19.2 87.65 0 top
CL2  0.1U_0201_10V6K  [C_0201]  20.61 90.41 90 top
CL3  0.1U_0201_10V6K  [C_0201]  23.96 90.1 0 top
CL4  0.1U_0201_10V6K  [C_0201]  23.96 90.99 0 top
CL5  0.1U_0201_10V6K  [C_0201]  20.18 83.96 180 top
CL6  0.1U_0201_10V6K  [C_0201]  26.45 83.68 90 bottom
CL7  12P_0402_50V8J  [C_0402]  19.19 84.97 0 top
CL8  0.1U_0201_10V6K  [C_0201]  29.02 88.26 0 top
CL9  0.1U_0201_10V6K  [C_0201]  29.02 88.9 0 top
CL10  0.1U_0201_10V6K  [C_0201]  28.67 83.62 0 top
CL11  0.1U_0201_10V6K  [C_0201]  20.07 80.7 180 top
CL12  0.1U_0201_10V6K  [C_0201]  22.89 90.53 90 top
CL13  0.1U_0201_10V6K  [C_0201]  142.27 94.89 90 bottom
CL14  0.1U_0201_10V6K  [C_0201]  141.69 94.89 90 bottom
CL15  4.7U_0402_6.3V6M  [C_0402]  28.66 84.77 0 top
CL16  1U_0201_6.3V6M  [C_0201]  23.96 91.88 0 top
CL17  4.7U_0402_6.3V6M  [C_0402]  20.18 81.85 180 top
CL18  0.1U_0201_10V6K  [C_0201]  23.91 83.04 90 bottom
CL19  1U_0201_6.3V6M  [C_0201]  46.2 49.06 270 top
CL20  10P_1206_2KVJ  [C_1206]  21.12 76.32 0 bottom
CL21  0.01U_0402_16V7K  [C_0402]  27.83 65.78 0 top
CLRP1  SHORT PADS  [SHORTPADS]  35.2 64.28 90 bottom
CS1  0.1U_0201_10V6K  [C_0201]  191.3 35.05 90 top
CS2  0.1U_0201_10V6K  [C_0201]  183.36 42.92 270 top
CS3  0.01U_0402_16V7K  [C_0402]  182.46 41.21 0 top
CS4  0.01U_0402_16V7K  [C_0402]  182.46 40.32 0 top
CS5  0.01U_0402_16V7K  [C_0402]  182.46 38.41 0 top
CS6  0.01U_0402_16V7K  [C_0402]  182.46 39.3 0 top
CS7  0.01U_0402_16V7K  [C_0402]  192.95 39.89 270 bottom
CS8  0.01U_0402_16V7K  [C_0402]  192.06 39.89 270 bottom
CS9  0.01U_0402_16V7K  [C_0402]  190.23 39.43 180 bottom
CS10  0.01U_0402_16V7K  [C_0402]  190.23 38.54 180 bottom
CS11  1000P_0402_50V7K  [C_0402]  181.59 38.73 180 bottom
CS12  0.1U_0201_10V6K  [C_0201]  181.43 37.02 180 bottom
CS13  10U_0402_6.3V6M  [C_0402]  181.59 37.78 180 bottom
CS14  0.01U_0402_16V7K  [C_0402]  186.24 61.39 90 bottom
CS15  0.01U_0402_16V7K  [C_0402]  187.13 61.39 90 bottom
CS16  0.01U_0402_16V7K  [C_0402]  190.15 61.39 90 bottom
CS17  0.01U_0402_16V7K  [C_0402]  189.26 61.39 90 bottom
CS18  0.1U_0201_10V6K  [C_0201]  102 44.74 270 top
CS19  10U_0402_6.3V6M  [C_0402]  106.02 45.86 270 top
CS20  1000P_0402_50V7K  [C_0402]  193.59 62.16 180 top
CS21  0.1U_0201_10V6K  [C_0201]  193.46 62.16 180 bottom
CS22  10U_0402_6.3V6M  [C_0402]  193.96 60.89 180 bottom
CS23  10U_0402_6.3V6M  [C_0402]  35.61 29.9 180 top
CS24  1U_0201_6.3V6M  [C_0201]  20.86 26.73 270 top
CS25  0.1U_0201_10V6K  [C_0201]  35.44 27.3 180 top
CS26  1000P_0402_50V7K~D  [C_0402]  35.61 29.01 180 top
CS27  22U_0603_6.3V6M  [C_0603]  36.1 30.98 180 top
CS28  22U_0603_6.3V6M  [C_0603]  21.88 26.86 270 top
CS29  47U_0805_6.3V6M  [C_0805]  23.4 26.98 270 top
CS30  47U_0805_6.3V6M  [C_0805]  36.25 32.51 180 top
CS31  0.22U_0402_10V6K  [C_0402]  31.09 36.9 270 bottom
CS32  0.22U_0402_10V6K  [C_0402]  30.2 36.9 270 bottom
CS33  0.22U_0402_10V6K  [C_0402]  28.99 36.9 270 bottom
CS34  0.22U_0402_10V6K  [C_0402]  28.1 36.9 270 bottom
CS35  0.1U_0201_10V6K  [C_0201]  186.15 35.66 270 top
CU1  0.1U_0201_10V6K  [C_0201]  218.39 29.01 180 top
CU2  47U_0805_6.3V4Z  [C_0805]  19.12 54.41 0 bottom
CU3  47U_0805_6.3V4Z  [C_0805]  19 53.78 0 top
CU4  10U_0402_6.3V6M  [C_0402]  19.15 56.7 0 bottom
CU5  0.1U_0201_10V6K  [C_0201]  19.3 58.22 0 bottom
CU7  4.7U_0805_10V6K  [C_0805]  20.65 43.11 0 top
CU8  0.1U_0201_10V6K  [C_0201]  20.7 41.65 0 top
CU10  0.1U_0201_10V6K  [C_0201]  25.29 51.68 0 bottom
CU11  0.1U_0201_10V6K  [C_0201]  25.29 52.64 0 bottom
CU12  0.1U_0201_10V6K  [C_0201]  22.22 39.81 0 top
CU13  0.1U_0201_10V6K  [C_0201]  22.22 38.79 0 top
CU15  47U_0805_6.3V4Z  [C_0805]  18.36 32.7 0 top
CU17  47U_0805_6.3V4Z  [C_0805]  18.36 34.48 0 top
CU18  10U_0402_6.3V6M  [C_0402]  18.51 36 0 top
CU19  0.1U_0201_10V6K  [C_0201]  18.66 37.02 0 top
CU20  0.1U_0201_10V6K  [C_0201]  23.07 37.9 0 bottom
CU21  0.1U_0201_10V6K  [C_0201]  23.07 38.92 0 bottom
CU22  4.7U_0805_10V6K  [C_0805]  201.75 46.35 0 bottom
CU23  0.1U_0201_10V6K  [C_0201]  202.37 44 0 bottom
CU24  0.1U_0201_10V6K  [C_0201]  54.22 78.1 0 top
CU25  0.1U_0201_10V6K  [C_0201]  198.54 39.48 90 bottom
CV1  4.7U_0603_6.3V6K  [C_0603]  219.17 59.37 0 top
CV2  0.1U_0201_10V6K  [C_0201]  209.42 53.53 0 bottom
CV3  0.1U_0201_10V6K  [C_0201]  209.42 52.89 0 bottom
CV4  0.1U_0201_10V6K  [C_0201]  208.02 52.13 0 bottom
CV5  0.1U_0201_10V6K  [C_0201]  208.02 51.49 0 bottom
CV6  0.1U_0201_10V6K  [C_0201]  209.55 50.48 0 bottom
CV7  0.1U_0201_10V6K  [C_0201]  209.55 49.84 0 bottom
CV8  0.1U_0402_25V6  [C_0402]  208.06 57.16 270 top
CV9  10U_0603_25V6M  [C_0603]  206.92 57.4 270 top
CV10  10P_0402_50V8J  [C_0402]  92.81 62.94 0 top
CV11  0.1U_0201_10V6K  [C_0201]  216.61 51.24 180 top
CV12  0.1U_0201_10V6K  [C_0201]  214.6 58.06 90 top
CV13  1U_0201_6.3V6M  [C_0201]  213.97 58.06 90 top
CV14  10P_0402_50V8J  [C_0402]  215.43 57.89 90 top
CV15  0.1U_0201_10V6K  [C_0201]  22.01 100.2 180 top
CV16  0.1U_0201_10V6K  [C_0201]  22.01 99.31 180 top
CV17  0.1U_0201_10V6K  [C_0201]  13.46 108.14 0 bottom
CV18  0.1U_0201_10V6K  [C_0201]  22.01 102.04 180 top
CV19  0.1U_0201_10V6K  [C_0201]  22.01 101.15 180 top
CV20  0.1U_0201_10V6K  [C_0201]  22.01 98.29 180 top
CV21  0.1U_0201_10V6K  [C_0201]  22.01 97.4 180 top
CV22  0.1U_0201_10V6K  [C_0201]  22.01 96.39 180 top
CV23  0.1U_0201_10V6K  [C_0201]  22.01 95.5 180 top
CV24  220P_0402_50V8J  [C_0402]  26.01 101.48 270 bottom
CW1  0.1U_0201_10V6K  [C_0201]  65.78 124.58 0 top
CW2  0.1U_0201_10V6K  [C_0201]  65.78 125.28 0 top
CW3  10U_0402_6.3V6M  [C_0402]  65.62 126.17 0 top
CW4  10U_0402_6.3V6M  [C_0402]  66.59 133.98 180 top
CW5  0.1U_0201_10V6K  [C_0201]  68.36 121.76 270 top
CW6  0.1U_0201_10V6K  [C_0201]  66.62 134.93 180 top
CW7  10P_0402_50V8J  [C_0402]  67.41 121.8 270 top
CW8  1U_0402_6.3V6K  [C_0402]  74.61 127.03 270 top
D1  -  [AZC199-02SPR7G_SOT23-3]  207.93 41.69 180 bottom
DA1  -  [L03ESDL5V0CC3-2_SOT23-3]  23.81 5.77 90 top
DA2  -  [L03ESDL5V0CC3-2_SOT23-3]  17.15 3.23 270 top
DA5  AZ5123-02S.R7G_SOT23-3  [AZ5123-02SPR7G_SOT23-3]  21.05 20.47 180 top
DA7  -  [BAT54CW_SOT323-3]  37.49 17.84 90 top
DA8  -  [L03ESDL5V0CC3-2_SOT23-3]  17.15 7.92 0 top
DA9  -  [L03ESDL5V0CC3-2_SOT23-3]  17.17 19.32 180 top
DA10  BAT54ATB_SOT-523-3  [BAT54ATB_SOT523-3]  20.01 12.25 90 top
DC1  CEST523NC5VB 3P C/A SOT-523  [TVNST52302AB0_SOT523-3]  118.71 88.24 270 top
DC2  -  [RB751V-40_SOD323-2]  158.46 76.64 180 bottom
DC3  CEST23LC3V3B 3P C/A SOT-23  [AZ5123-02SPR7G_SOT23-3]  102.48 82.23 90 top
DC4  -  [BAS40C_SOT23-3]  206.28 38.51 0 top
DD1  CEST23LC3V3B 3P C/A SOT-23  [AZ5123-02SPR7G_SOT23-3]  68.56 40.9 0 top
DD2  CEST23LC3V3B 3P C/A SOT-23  [AZ5123-02SPR7G_SOT23-3]  65.48 50.03 270 top
DE1  -  [RB751V-40_SOD323-2]  41.31 85.52 270 bottom
DE2  -  [CK0402101V05_0402-2]  32.29 62.59 0 top
DH1  -  [RB751V-40_SOD323-2]  88.78 124.2 180 bottom
DH2  -  [RB751V-40_SOD323-2]  90.74 124.2 0 bottom
DV1  -  [BAT54CW_SOT323-3]  52.99 89.21 270 top
EC1  1000P_0402_50V7K  [C_0402]  221.84 65.83 90 top
EC2  0.1U_0201_10V6K  [C_0201]  224.05 61.65 0 top
ED1  -  [L03ESDL5V0CG3-2_SOT-523-3]  210.37 45.84 0 top
ED2  -  [L03ESDL5V0CG3-2_SOT-523-3]  208.38 46.54 270 bottom
ED3  -  [L03ESDL5V0CC3-2_SOT23-3]  218.89 61.97 270 top
EL1  -  [L05ESDL5V0NA-4_SLP2510P8-10-9]  24.78 81.08 0 top
EU1  -  [AZC199-02SPR7G_SOT23-3]  221.1 36 270 bottom
EU2  -  [TVNST52302AB0_SOT523-3]  222.03 28.82 180 top
EU3  -  [AZC199-02SPR7G_SOT23-3]  21.2 48.06 270 bottom
EU4  -  [L05ESDL5V0NA-4_SLP2510P8-10-9]  20.04 50.75 270 bottom
EU5  -  [AZC199-02SPR7G_SOT23-3]  20.89 41.42 270 bottom
EU6  -  [L05ESDL5V0NA-4_SLP2510P8-10-9]  18.27 36.65 270 bottom
F1  1A_65V_T0603FF1000TM  [F_T0603FF1000TM]  217.2 48.43 270 top
F2  1A_65V_T0603FF1000TM  [F_T0603FF1000TM]  219.88 46.03 0 top
F3  0.5A_13.2V_MF-NSMF050-2  [F_MF-NSMF050-2]  99.79 29.42 90 bottom
FD1  FIDUCAL  [FIDUCIAL_C40M80]  6.38 125.22 0 top
FD2  FIDUCAL  [FIDUCIAL_C40M80]  222.54 32.7 0 top
FD3  FIDUCAL  [FIDUCIAL_C40M80]  6.38 125.22 180 bottom
FD4  FIDUCAL  [FIDUCIAL_C40M80]  222.54 32.7 180 bottom
FV1  SMD1812P150TF/24 1.5A UL/CSA/TUV  [F_SMD1812P110TF-24]  202.65 56.83 0 bottom
FV2  1.5A_6V_1206L150PR~D  [F_1206L150PR]  12.04 108.89 90 bottom
H1  HOLEA  [H_3P0-G]  6.85 130.5 0 top
H2  HOLEA  [H_3P0-G]  99 154 0 top
H4  HOLEA  [H_3P0-G]  7.9 85.8 0 top
H5  HOLEA  [H_3P0-G]  8 41.2 0 top
H6  HOLEA  [H_3P0-G]  207.45 63.85 0 top
H7  HOLEA  [H_3P0-G]  141.55 27.1 0 top
H8  HOLEA  [H_3P3-G]  6.9 112.6 0 top
H12  HOLEA  [H_3P2]  45.5 130.8 0 top
H13  HOLEA  [H_3P0X4P0]  213.85 65.5 90 top
H14  HOLEA  [H_5P6N]  19.1 111.3 0 top
HCPU1  HOLEA  [H_3P9]  113.08 110.41 0 top
HCPU2  HOLEA  [H_3P9]  137.38 110.41 0 top
HCPU3  HOLEA  [H_3P9]  113.08 49.41 0 top
HCPU4  HOLEA  [H_3P9]  137.38 49.41 0 top
J1  -  [JUMP_43X118]  34.12 50.49 0 top
J2  -  [JUMP_43X79]  34.12 45.86 0 top
J3  -  [JUMP_43X79]  162.59 47.13 90 top
J4  -  [JUMP_43X118]  28.2 49 0 top
J5  -  [JUMP_43X118]  96.9 57.56 270 top
JDIMM1  DEREN_40-42271-26001RHF  [LOTES_ADDR0206-P001A02_260P]  79.15 112.24 90 bottom
JEDP1  ACES_51540-04001-P01  [ACES_51540-04001-P01_40P]  212.37 60.45 270 bottom
JFAN1  ACES_50224-00401-001  [ACES_50224-00401-001_4P]  181.5 70.69 90 bottom
JFP1  ACES_51522-00801-001  [ACES_51522-00801-001_8P]  221 30.6 180 bottom
JHDD1  ACES_51625-01201-001  [ACES_51625-01201-001_12P]  190.2 35.7 180 bottom
JHDMI1  CONCR_099AKAC19NBLCNF  [ACON_HMRF6-AK120C_19P-T]  11.05 92.35 90 bottom
JHDT1  SAMTE_ASP-136446-07-B  [SAMTE_ASP-136446-07-B_20P-T]  85 131.44 0 bottom
JHP1  YUQIU_PJ753-F07J1BE-B  [YUQIU_PJ753-F07J1BE-B_7P-T]  12.65 7.9 90 bottom
JIOB1  ACES_51524-0160N-001  [ACES_51524-0160N-001_16P]  213.2 36.8 180 bottom
JKB1  HEFEN_AFB02-S30F1A-HF  [HEFEN_AFB02-S30F1A-HF_30P-T]  59.75 34.2 180 bottom
JKBBL1  ACES_51575-00401-001  [ACES_51575-00401-001_4P]  95.05 34.52 180 bottom
JLAN1  SANTA_130460-N  [SINGA_2RJ3076-078211F_8P-T]  12.95 77.72 90 bottom
JODD1  ACES_50673-0120N-001  [ACES_50673-0120N-001_12P-T]  185.2 64.3 180 bottom
JP2  -  [JUMP_43X39]  208.77 35.94 180 top
JP3  -  [JUMP_43X79]  184.31 40.23 270 bottom
JP4  -  [JUMP_43X79]  196.74 60.61 180 bottom
JP5  -  [JUMP_43X79]  38.03 31.75 0 top
JP6  -  [JUMP_43X39]  40.92 51.24 0 top
JPWR1  JXT_FP226H-004S1AM  [JXT_FP226H-004S1AM_4P]  221.2 63.65 0 bottom
JRTC1  LOTES_AAA-BAT-054-K01  [LOTES_AAA-BAT-054-K01_2P]  54.98 45 270 bottom
JSPK1  ACES_50224-00401-001  [ACES_50224-00401-001_4P]  16.4 5.88 180 bottom
JSSD1  LCN_DAN05-67306-0103  [LCN_DAN05-67306-0103_75P]  39.38 34.03 180 bottom
JTP1  ACES_51524-0080N-001  [ACES_51524-0080N-001_8P]  125.05 30.5 180 bottom
JUSB1  ACON_TARAN-9R1391  [ACON_TARAN-9R1391_9P]  15.88 56.65 90 bottom
JUSB2  ACON_TARAN-9R1391  [ACON_TARAN-9R1391_9P]  15.88 32.75 90 bottom
JWLAN1  LOTES_APCI0136-P001A  [LOTES_APCI0136-P001A_75P]  79.03 121.55 90 bottom
L1  MCM1012B900F06BP_4P  [INPAQ_MCM1012B900F06BP_4P]  205.91 46.99 0 bottom
L5  BLM15PX221SN1D_2P  [MURAT_BLM15PX221SN1D_2P]  36.72 11.3 180 top
LA1  BLM15PX330SN1D_2P  [MURAT_BLM15PX330SN1D_2P]  21.71 14.85 0 top
LA2  0_0402_5%  [R_0402]  22.72 13.01 180 top
LA3  0_0402_5%  [R_0402]  22.72 11.49 180 top
LA13  BLM15PX330SN1D_2P  [MURAT_BLM15PX330SN1D_2P]  18.47 14.85 0 top
LA15  HCB1005KF-800T20  [MURAT_BLM15PX221SN1D_2P]  24.03 1.86 180 top
LA16  HCB1005KF-800T20  [MURAT_BLM15PX221SN1D_2P]  25.99 2.79 180 top
LA17  HCB1005KF-800T20  [MURAT_BLM15PX221SN1D_2P]  28.09 5.65 180 top
LA18  HCB1005KF-800T20  [MURAT_BLM15PX221SN1D_2P]  28.14 4.57 180 top
LC1  5A_Z80_0805_2P  [KC_FBMA-L11-201209-121LMA50_2P]  93.37 54.08 0 top
LC2  5A_Z80_0805_2P  [KC_FBMA-L11-201209-121LMA50_2P]  93.37 51.96 0 top
LE1  BLM15BD121SN1D_2P  [MURAT_BLM15BD121SN1D_2P]  54.79 70.21 180 top
LE2  BLM15BD121SN1D_2P  [MURAT_BLM15BD121SN1D_2P]  51.49 65.59 0 top
LED1  LTW-295DSKS-5A_YEL-WHITE~D  [LED_LTW-295DSKS-5A_4P]  3.25 133.05 270 bottom
LU1  INPAQ HCM1012GD670A05P  [INPAQ_HCM1012GH900BP_4P-NPM]  22.59 50.35 0 bottom
LU2  INPAQ HCM1012GD670A05P_4P  [INPAQ_HCM1012GH900BP_4P-NPM]  22.59 52.2 0 bottom
LU3  MCM1012B900F06BP_4P  [INPAQ_MCM1012B900F06BP_4P]  23.28 44.5 270 bottom
LU4  INPAQ HCM1012GD670A05P  [INPAQ_HCM1012GH900BP_4P-NPM]  20.49 36.51 0 bottom
LU5  INPAQ HCM1012GD670A05P  [INPAQ_HCM1012GH900BP_4P-NPM]  20.49 38.16 0 bottom
LU6  MCM1012B900F06BP_4P  [INPAQ_MCM1012B900F06BP_4P]  23.03 39.94 0 bottom
LU7  MCM1012B900F06BP_4P  [INPAQ_MCM1012B900F06BP_4P]  210.21 39.17 180 bottom
LU8  MCM1012B900F06BP_4P  [INPAQ_MCM1012B900F06BP_4P]  206.53 39.17 180 bottom
LV1  HCB2012KF-221T30_2P  [TAI-T_HCB2012KF-221T30_2P]  217.44 55.68 180 top
LV2  HCM1012GH900BP_4P  [INPAQ_HCM1012GH900BP_4P]  18.59 100.07 0 top
LV3  HCM1012GH900BP_4P  [INPAQ_HCM1012GH900BP_4P]  18.59 101.91 0 top
LV4  HCM1012GH900BP_4P  [INPAQ_HCM1012GH900BP_4P]  18.6 98.17 0 top
LV5  HCM1012GH900BP_4P  [INPAQ_HCM1012GH900BP_4P]  18.6 96.2 0 top
NOREF  -  []  93.44 -29.21 0 top
NOREF#2  -  []  7.9 85.8 0 top
NOREF#3  -  []  213.85 65.5 0 top
NOREF#4  -  []  90.49 77.38 0 top
NOREF#5  -  []  30.77 119.25 0 top
NOREF#6  -  []  113.08 110.41 0 top
NOREF#7  -  []  7.4 86.8 0 top
NOREF#8  -  []  6.85 130.5 0 top
NOREF#9  -  []  137.38 49.41 0 top
NOREF#10  -  []  8 41.2 90 top
NOREF#11  -  []  195.26 31.75 0 top
NOREF#12  -  []  113.08 49.41 0 top
NOREF#13  -  []  137.38 110.41 0 top
NOREF#14  -  []  65.41 15.36 0 top
NOREF#15  -  []  164.5 35.93 0 top
NOREF#16  -  []  141.55 27.1 180 top
NOREF#17  -  []  6.9 112.6 90 top
NOREF#18  -  []  118.84 129.09 0 top
NOREF#19  -  []  87.16 194.5 0 top
NOREF#20  -  []  99 154 0 top
NOREF#21  -  []  176.06 34.84 0 top
NOREF#22  -  []  45.5 130.8 0 top
NOREF#23  -  []  207.45 63.85 0 top
NOREF#24  -  []  160.91 85.32 180 bottom
NOREF#25  -  []  88.46 56.27 180 bottom
NOREF#26  -  []  106 114.26 90 bottom
PBATT1  -  [ACES_50458-01001-P01_10P-T]  172.95 39.98 180 bottom
PC1  1000P_0402_50V7K  [C_0402]  87.4 147.92 90 top
PC2  100P_0402_50V8J  [C_0402]  86.45 147.92 90 top
PC3  1000P_0402_50V7K  [C_0402]  90.01 147.92 90 top
PC4  100P_0402_50V8J  [C_0402]  90.96 147.92 90 top
PC11  0.01U_0402_25V7K  [C_0402]  165.24 46.82 90 bottom
PC12  1000P_0402_50V7K  [C_0402]  169.57 42.73 0 bottom
PC13  .1U_0402_16V7K  [C_0402]  171.8 54.4 90 top
PC14  .1U_0402_16V7K  [C_0402]  197.72 45.46 180 top
PC15  10P_0402_25V8J  [C_0402]  88.36 147.92 90 top
PC301  1000P_0402_50V7K  [C_0402]  48.41 111.82 0 top
PC302  2200P_0402_50V7K  [C_0402]  48.41 111.82 0 bottom
PC303  10U_0603_25V6M  [C_0603]  48.17 112.96 0 top
PC304  10U_0603_25V6M  [C_0603]  48.17 112.96 0 bottom
PC305  0.1U_0402_25V6  [C_0402]  48.41 110.8 0 bottom
PC306  1000P_0402_50V7K  [C_0402]  48.41 110.8 0 top
PC307  0.1U_0402_10V7K  [C_0402]  47.6 104.15 270 bottom
PC308  4.7U_0402_6.3V6M  [C_0402]  52.12 104.58 180 bottom
PC309  680P_0603_50V7K  [C_0603]  52.23 104.32 0 top
PC310  22U_0603_6.3V6M  [C_0603]  47.66 94.42 180 bottom
PC311  22U_0603_6.3V6M  [C_0603]  47.66 94.42 180 top
PC312  22U_0603_6.3V6M  [C_0603]  47.66 93.15 180 bottom
PC313  22U_0603_6.3V6M  [C_0603]  47.66 93.15 180 top
PC314  22U_0603_6.3V6M  [C_0603]  47.66 91.88 180 bottom
PC315  1000P_0402_25V8J  [C_0402]  54.5 107.63 0 bottom
PC316  22U_0603_6.3V6M  [C_0603]  47.66 91.88 180 top
PC317  1U_0402_25V6K  [C_0402]  54.38 108.77 0 bottom
PC501  1000P_0402_50V7K  [C_0402]  38.38 111.31 0 top
PC502  2200P_0402_50V7K  [C_0402]  38.38 111.31 0 bottom
PC503  10U_0603_25V6M  [C_0603]  38.39 112.45 0 bottom
PC504  10U_0603_25V6M  [C_0603]  38.39 112.45 0 top
PC505  0.1U_0402_25V6  [C_0402]  38.38 110.29 0 bottom
PC506  1000P_0402_50V7K  [C_0402]  38.38 110.29 0 top
PC507  0.1U_0402_10V7K  [C_0402]  37.56 103.64 270 bottom
PC508  4.7U_0402_6.3V6M  [C_0402]  42.08 104.07 180 bottom
PC509  680P_0603_50V7K  [C_0603]  41.25 102.61 90 top
PC510  22U_0603_6.3V6M  [C_0603]  38.46 94.1 180 bottom
PC511  22U_0603_6.3V6M  [C_0603]  38.45 92.83 180 bottom
PC512  22U_0603_6.3V6M  [C_0603]  38.43 91.56 180 bottom
PC513  22U_0603_6.3V6M  [C_0603]  38.45 92.83 180 top
PC514  22U_0603_6.3V6M  [C_0603]  38.45 94.1 180 top
PC515  4.7U_0402_6.3V6M  [C_0402]  44.47 105.34 0 bottom
PC516  4.7U_0402_6.3V6M  [C_0402]  47.42 104.96 180 top
PC517  1000P_0402_25V8J  [C_0402]  44.47 107.12 0 bottom
PC518  22U_0603_6.3V6M  [C_0603]  38.45 90.36 180 top
PC519  22U_0603_6.3V6M  [C_0603]  38.45 91.56 180 top
PC520  22U_0603_6.3V6M  [C_0603]  38.45 90.36 180 bottom
PC801  10U_0402_6.3V6M  [C_0402]  146.9 47.18 0 bottom
PC802  1U_0402_10V6K  [C_0402]  143.27 47.16 0 bottom
PC803  .1U_0402_16V7K  [C_0402]  149.64 43.1 90 bottom
PC804  10U_0402_6.3V6M  [C_0402]  147.3 40.57 180 bottom
PC805  0.1U_0402_10V7K  [C_0402]  150.07 40.83 0 top
PC901  82P_0201_50V8J  [C_0201]  172.5 43.52 90 top
PC902  0.01UF 25V +-10% X7R 0402  [C_0402]  170.61 46.36 180 top
PC903  82P_0201_50V8J  [C_0201]  174.82 46.92 180 top
PC904  82P_0201_50V8J  [C_0201]  171.42 49.12 270 top
PC905  0.22U_0402_10V K  [C_0402]  172.18 48.69 90 top
PC908  1U_0201_6.3V6M  [C_0201]  170.51 45.6 180 top
PC909  1U_0201_6.3V6M  [C_0201]  170.51 45.02 180 top
PC910  1U_0201_6.3V6M  [C_0201]  170.51 47.13 180 top
PC911  1U_0201_6.3V6M  [C_0201]  170.51 47.7 180 top
PC1801  22U_0603_6.3V6M  [C_0603]  167.66 52.95 180 bottom
PC1802  22U_0603_6.3V6M  [C_0603]  158.09 49.27 0 bottom
PC1803  22U_0603_6.3V6M  [C_0603]  158.09 48.06 0 bottom
PC1804  22U_0603_6.3V6M  [C_0603]  158.09 50.48 0 bottom
PC1805  0.1U_0402_10V7K  [C_0402]  164.11 57.53 0 bottom
PC1806  680P_0402_50V7K  [C_0402]  163.34 52.38 0 top
PC1807  22P_0402_50V8J  [C_0402]  166.9 58.29 0 bottom
PC2501  22U_0603_6.3V6M  [C_0603]  62.96 81.72 180 bottom
PC2502  22U_0603_6.3V6M  [C_0603]  63.22 72.83 0 bottom
PC2503  0.1U_0402_10V6K  [C_0402]  60.61 81.77 90 bottom
PC2504  2.2U_0402_6.3V6M  [C_0402]  65.31 79.61 90 bottom
PC2505  0.01U_0402_25V7K  [C_0402]  62.21 72.83 180 bottom
PCB01  0.1U_0402_25V6  [C_0402]  181.01 65.9 90 top
PCB02  0.01U_0402_25V7K  [C_0402]  191.37 50.73 180 top
PCB03  0.1U_0402_25V6  [C_0402]  191.42 52.71 270 bottom
PCB04  0.033U_0402_25V7K  [C_0402]  189.87 52.57 270 top
PCB05  1U_0402_25V6K  [C_0402]  191.44 50.88 180 bottom
PCB06  0.47U_0402_25V6K  [C_0402]  189.76 47.56 0 bottom
PCB07  4.7U_0603_25V6K  [C_0603]  191.93 55.25 270 bottom
PCB08  2.2U_0402_16V6K  [C_0402]  193.01 54.17 270 bottom
PCB09  10P_0402_50V8J  [C_0402]  198.97 51.76 0 bottom
PCB10  2200P_0402_25V7K  [C_0402]  53.92 72.8 0 top
PCB11  0.033U_0402_25V7K  [C_0402]  199.88 49.94 270 top
PCB12  560P_0402_50V7K  [C_0402]  198.97 49.97 0 bottom
PCB13  0.1U_0402_25V6  [C_0402]  53.49 67.5 0 top
PCB14  0.1U_0402_25V6  [C_0402]  198.97 48.19 0 bottom
PCB15  0.1U_0402_25V6  [C_0402]  196.93 45.78 0 bottom
PCB16  0.22U_0402_25V6K  [C_0402]  197.87 44.84 0 bottom
PCB17  1U_0402_25V6K  [C_0402]  197.01 44.84 180 bottom
PCB18  0.47U_0402_25V6K  [C_0402]  194.34 45.02 180 bottom
PCB19  2.2U_0402_16V6K  [C_0402]  190.34 45.28 270 bottom
PCB20  10U_0603_25V6M  [C_0603]  186.95 51.63 0 bottom
PCB21  10U_0603_25V6M  [C_0603]  186.89 51.38 0 top
PCB22  10U_0603_25V6M  [C_0603]  186.95 52.87 0 bottom
PCB23  10U_0603_25V6M  [C_0603]  186.89 52.61 0 top
PCB24  0.1U_0402_25V6  [C_0402]  186.9 49.33 0 bottom
PCB25  2200P_0402_50V7K  [C_0402]  186.91 50.41 0 bottom
PCB26  1000P_0402_50V7K  [C_0402]  186.84 49.33 0 top
PCB27  1000P_0402_50V7K  [C_0402]  186.81 50.3 0 top
PCB28  0.1U_0402_25V6  [C_0402]  174.72 56.13 270 bottom
PCB29  680P_0603_50V7K  [C_0603]  184.13 47.2 0 top
PCB30  10U_0603_25V6M  [C_0603]  164.12 46.86 90 bottom
PCB31  10U_0603_25V6M  [C_0603]  168.92 46.82 90 bottom
PCB32  10U_0603_25V6M  [C_0603]  188.92 58 90 top
PCB33  10U_0603_25V6M  [C_0603]  167.65 46.82 90 bottom
PCB34  10U_0603_25V6M  [C_0603]  166.38 46.82 90 bottom
PCB36  0.047U_0402_25V7K  [C_0402]  198.94 53.74 270 top
PCB70  15U_B2_25VM_R100M  [C_B2]  183.34 61.02 0 bottom
PCH01  0.1U_0402_25V6  [C_0402]  164.47 67.6 180 bottom
PCH02  2200P_0402_50V7K  [C_0402]  164.47 66.64 180 bottom
PCH03  10U_0603_25V6M  [C_0603]  164.09 68.79 180 top
PCH04  10U_0603_25V6M  [C_0603]  164.09 68.79 180 bottom
PCH05  22U_0603_6.3V6M  [C_0603]  158.23 71.98 0 bottom
PCH06  22U_0603_6.3V6M  [C_0603]  158.23 69.49 0 bottom
PCH07  22U_0603_6.3V6M  [C_0603]  158.23 71.98 0 top
PCH08  22U_0603_6.3V6M  [C_0603]  158.23 70.76 0 top
PCH09  0.1U_0402_25V6  [C_0402]  165.58 66.74 90 bottom
PCH10  1U_0402_10V6K  [C_0402]  167.36 65.83 90 bottom
PCH11  1U_0402_10V6K  [C_0402]  167.55 62.46 0 bottom
PCH12  0.1U_0402_10V6K  [C_0402]  163.81 60.79 180 bottom
PCH13  680P_0603_50V7K  [C_0603]  161.33 64.99 0 top
PCH14  330P_0402_50V7K  [C_0402]  168.25 66.75 270 bottom
PCH15  1000P_0402_50V7K  [C_0402]  164.47 66.64 180 top
PCH16  1000P_0402_50V7K  [C_0402]  164.47 67.6 180 top
PCH17  22U_0603_6.3V6M  [C_0603]  158.23 70.76 0 bottom
PCH18  22U_0603_6.3V6M  [C_0603]  158.23 69.49 0 top
PCH19  22U_0603_6.3V6M  [C_0603]  158.21 73.21 0 top
PCH20  22U_0603_6.3V6M  [C_0603]  158.21 73.21 0 bottom
PCM01  0.1U_0402_25V6  [C_0402]  63.46 104.64 0 bottom
PCM02  2200P_0402_50V7K  [C_0402]  63.46 105.66 0 bottom
PCM03  10U_0603_25V6M  [C_0603]  63.5 106.8 0 bottom
PCM04  10U_0603_25V6M  [C_0603]  63.5 106.8 0 top
PCM05  22U_0603_6.3V6M  [C_0603]  62.52 86.93 180 top
PCM06  22U_0603_6.3V6M  [C_0603]  62.52 88.2 180 top
PCM07  22U_0603_6.3V6M  [C_0603]  62.52 89.47 180 bottom
PCM08  22U_0603_6.3V6M  [C_0603]  62.52 86.93 180 bottom
PCM09  22U_0603_6.3V6M  [C_0603]  62.52 88.2 180 bottom
PCM10  22U_0603_6.3V6M  [C_0603]  62.52 89.47 180 top
PCM11  680P_0402_50V7K  [C_0402]  63.46 103.69 0 top
PCM12  0.1U_0402_10V7K  [C_0402]  64.23 108.44 90 bottom
PCM13  2.2U_0402_6.3V6M  [C_0402]  67.01 111.55 0 bottom
PCM14  2.2U_0402_6.3V6M  [C_0402]  67.01 114.93 0 bottom
PCM15  0.1U_0402_10V7K  [C_0402]  63.19 116.06 90 bottom
PCM16  0.1U_0402_10V7K  [C_0402]  62.29 116.06 90 bottom
PCM17  220P_0402_25V8J  [C_0402]  59.93 116.14 180 bottom
PCM18  .1U_0402_16V7K  [C_0402]  59.01 114.49 0 bottom
PCM19  0.033U_0402_16V7K  [C_0402]  59.93 112.77 180 bottom
PCM20  22U_0603_6.3V6M  [C_0603]  60.55 110.29 90 bottom
PCM22  1000P_0402_50V7K  [C_0402]  63.46 104.64 0 top
PCM23  1000P_0402_50V7K  [C_0402]  63.46 105.66 0 top
PCZ00  33U_D2_25VM_R60M  [C_D2]  150.9 130 90 bottom
PCZ02  10U_0603_25V6M  [C_0603]  156.75 113.98 0 bottom
PCZ03  10U_0603_25V6M  [C_0603]  156.75 113.98 0 top
PCZ04  330P_0402_50V7K  [C_0402]  156.67 140.22 90 top
PCZ06  390P_0402_50V7K  [C_0402]  154.94 140.22 90 top
PCZ07  1000P_0402_50V7K  [C_0402]  154.96 142.87 270 top
PCZ08  220P_0402_50V8J  [C_0402]  153.21 141.14 270 top
PCZ09  0.22U_0402_16V7K  [C_0402]  153.84 138.21 180 top
PCZ10  330P_0402_50V7K  [C_0402]  153.23 143.73 270 top
PCZ11  0.022U_0402_25V7K  [C_0402]  159.5 141.35 180 top
PCZ12  0.1U_0402_25V6  [C_0402]  159.43 142.43 180 top
PCZ13  680P_0603_50V7K  [C_0603]  155.48 108.96 90 top
PCZ14  0.1U_0402_25V6  [C_0402]  157.64 142.38 270 top
PCZ15  220P_0402_50V7K  [C_0402]  159.43 144.2 180 top
PCZ18  1000P_0402_50V7K  [C_0402]  149.89 145.23 270 top
PCZ37  330P_0402_50V7K  [C_0402]  140.17 137.17 270 top
PCZ38  0.22U_0402_16V7K  [C_0402]  146.01 133.85 0 top
PCZ39  10U_0603_25V6M  [C_0603]  153.7 121.28 270 bottom
PCZ53  0.1U_0402_25V6  [C_0402]  140.66 141.45 90 top
PCZ54  680P_0603_50V7K  [C_0603]  151.16 119.25 0 top
PCZ55  1U_0603_10V6K  [C_0603]  151.16 135.49 270 top
PCZ56  2200P_0402_50V7K  [C_0402]  151.67 121.29 270 bottom
PCZ57  680P_0402_50V7K  [C_0402]  142.76 136.19 0 top
PCZ58  0.01U_0402_50V7K  [C_0402]  140.42 140.58 0 top
PCZ59  330P_0402_50V7K  [C_0402]  143.67 138.96 180 top
PCZ60  1000P_0402_50V7K  [C_0402]  141.85 138.9 270 top
PCZ61  820P_0402_50V7K  [C_0402]  142.62 141.08 270 top
PCZ62  1000P_0402_50V7K  [C_0402]  144.69 144.92 270 top
PCZ63  1U_0603_10V6K  [C_0603]  148.62 134.11 0 top
PCZ64  1U_0402_25V6K  [C_0402]  147.42 144.95 90 top
PCZ65  0.1U_0402_25V6  [C_0402]  139.3 142.04 180 top
PCZ66  0.022U_0402_25V7K  [C_0402]  141.55 141.46 90 top
PCZ67  10U_0603_25V6M  [C_0603]  154.97 121.28 270 bottom
PCZ68  100P_0402_50V8J  [C_0402]  142.74 137.13 0 top
PCZ69  0.1U_0402_25V6  [C_0402]  152.56 121.29 270 bottom
PCZ70  10U_0603_25V6M  [C_0603]  153.7 121.28 270 top
PCZ71  2200P_0402_50V7K  [C_0402]  156.8 112.83 0 bottom
PCZ72  1000P_0402_50V7K  [C_0402]  156.8 112.83 0 top
PCZ73  0.1U_0402_25V6  [C_0402]  156.8 111.95 0 bottom
PCZ74  1000P_0402_50V7K  [C_0402]  156.8 111.95 0 top
PCZ75  1000P_0402_50V7K  [C_0402]  151.67 121.29 270 top
PCZ76  1000P_0402_50V7K  [C_0402]  152.56 121.29 270 top
PCZ77  330U_D2_2V_Y  [C_D2]  135.66 122.89 90 bottom
PCZ78  330U_D2_2V_Y  [C_D2]  135.33 118.32 0 bottom
PCZ79  22U_0603_6.3V6M  [C_0603]  138.64 127.82 90 bottom
PCZ80  22U_0603_6.3V6M  [C_0603]  132.21 115.21 0 bottom
PCZ86  330U_D2_2V_Y  [C_D2]  151.29 94.4 90 bottom
PCZ87  330U_D2_2V_Y  [C_D2]  146.59 94.4 90 bottom
PCZ88  22U_0603_6.3V6M  [C_0603]  160.5 94.17 0 top
PCZ89  22U_0603_6.3V6M  [C_0603]  160.5 92.9 0 top
PCZ90  33U_25V_M  [C_6P3X4P5]  150.9 130.4 90 bottom
PCZ91  22U_0603_6.3V6M  [C_0603]  145.13 109.53 0 top
PCZ92  22U_0603_6.3V6M  [C_0603]  145.13 105.72 0 top
PCZ93  22U_0603_6.3V6M  [C_0603]  145.13 108.26 0 top
PCZ94  22U_0603_6.3V6M  [C_0603]  145.13 109.53 0 bottom
PCZ95  22U_0603_6.3V6M  [C_0603]  145.13 106.99 0 top
PCZ96  22U_0603_6.3V6M  [C_0603]  145.13 108.26 0 bottom
PCZ97  22U_0603_6.3V6M  [C_0603]  145.13 106.99 0 bottom
PCZ98  22U_0603_6.3V6M  [C_0603]  145.13 105.72 0 bottom
PCZ101  22U_0603_6.3V6M  [C_0603]  158.97 90.61 270 top
PCZ102  22U_0603_6.3V6M  [C_0603]  157.51 90.61 270 top
PCZ103  22U_0603_6.3V6M  [C_0603]  158.97 90.61 270 bottom
PCZ104  22U_0603_6.3V6M  [C_0603]  157.51 90.61 270 bottom
PD1  -  [TVNST52302AB0_SOT523-3]  75.4 143.23 180 top
PD2  -  [BAV99W_SC70-3]  81.52 148.18 0 top
PD3  -  [BAV99W_SC70-3]  82.94 142.96 180 top
PD5  -  [L03ESDL5V0CG3-2_SOT-523-3]  161.91 38.42 180 top
PD6  -  [L03ESDL5V0CG3-2_SOT-523-3]  168.06 39.49 270 top
PD14  AZ4024-02S_SOT23  [PJSOT24C_SOT23-3]  179.13 55.65 180 top
PD501  -  [RB751V-40_SOD323-2]  43.22 105.34 0 top
PD900  -  [BAT54CW_SOT323-3]  167.23 50.86 0 top
PD901  -  [RB520SM-30T2R_EMD2-2]  174.7 45.14 0 top
PD902  -  [RB520SM-30T2R_EMD2-2]  173.86 50.67 180 top
PDB01  -  [LRB715FT1G_SOT323-3]  188.7 56.7 90 bottom
PDB13  AZ4024-02S_SOT23  [PJSOT24C_SOT23-3]  183.16 55.65 180 top
PDM01  -  [RB751V-40_SOD323-2]  67.34 111.94 270 top
PH1  100K_0402_1%_B25/50 4250K  [R_0402]  122.96 58 90 top
PHZ1  10K_0402_5%_ERTJ0ER103J  [R_0402]  161.71 96.57 90 bottom
PHZ2  470K_0402_5%_TSM0B474J4702RE  [R_0402]  149.7 108.57 90 bottom
PHZ3  470K_0402_5%_TSM0B474J4702RE  [R_0402]  158.82 126.77 90 bottom
PHZ4  10K_0402_5%_ERTJ0ER103J  [R_0402]  145.27 128.96 180 bottom
PJP1  JUMP_43X79  [JUMP_43X79-NPM]  88.86 145.04 0 top
PJP2  JUMP_43X79  [JUMP_43X79-NPM]  76.53 145.28 180 bottom
PJP3  JUMP_43X79  [JUMP_43X79-NPM]  166.59 44.74 270 bottom
PJP301  JUMP_43X39  [JUMP_43X39-NPM]  45.61 112.96 0 bottom
PJP302  -  [JUMP_43X118]  50.9 92.62 270 bottom
PJP501  JUMP_43X79  [JUMP_43X79-NPM]  35.91 113.26 270 bottom
PJP502  -  [JUMP_43X118]  41.75 92.18 270 bottom
PJP801  -  [JUMP_43X79]  150.26 48.86 270 bottom
PJP802  -  [JUMP_43X79]  149.9 38.86 90 bottom
PJP1801  -  [JUMP_43X39]  169.35 55.69 270 bottom
PJP1802  -  [JUMP_43X79]  155.67 50.9 270 bottom
PJP2501  -  [JUMP_43X39]  65.39 82.35 180 bottom
PJP2502  -  [JUMP_43X39]  63.92 71.38 270 bottom
PJPB01  JUMP_43X118  [JUMP_43X118-NPM]  183.19 55.61 0 bottom
PJPDC1  ACES_50458-00601-001  [ACES_50458-00601-001_6P-T]  81.2 144.05 0 bottom
PJPH01  JUMP_43X39  [JUMP_43X39-NPM]  163.82 71.43 270 bottom
PJPH02  -  [JUMP_43X118]  154.7 70.23 180 bottom
PJPM01  JUMP_43X39  [JUMP_43X39-NPM]  60.73 106.48 0 bottom
PJPM02  -  [JUMP_43X118]  66.1 87.94 0 bottom
PJPM03  -  [JUMP_43X39]  60.88 110.29 180 top
PJPZ01  JUMP_43X79  [JUMP_43X79-NPM]  160.5 121.83 180 bottom
PL1  5A Z150 20M 1210_2P  [5A_Z150_1210_2P]  88.04 145.01 0 top
PL2  5A Z150 20M 1210_2P  [5A_Z150_1210_2P]  77.34 145.17 180 bottom
PL3  BLM15AG102SN1D_2P  [MURAT_BLM15AG102SN1D_2P]  76.93 143.76 90 top
